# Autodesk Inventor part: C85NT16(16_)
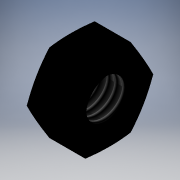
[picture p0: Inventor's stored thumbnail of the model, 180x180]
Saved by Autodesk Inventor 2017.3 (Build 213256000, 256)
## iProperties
Part Number: C85NT16(16_)
Material: Generic
Catalog Web Link: www.cadenas.de
Description: C85/CD85 ROD_NUT-ISO Standard Air Cylinder:Standard Type Double Acting Single Rod
Vendor: SMC
Document SubType Name: Modeling
Designer: partserver
Manufacturer: SMC
Mass: 0.332201 g
Surface Area: 3.72276 cm^2
Volume: 0.332201 cm^3
Density: 1 g/cm^3
Appearance: PSOLRGB-0-0-0
Category: PARTsolutions
Company: SMC
Title: C85NT16
Author: Cadenas PARTsolutions
Comments: ISO Standard Air Cylinder:Standard Type Double Acting Single Rod
PSOL_IDENT_0: {$CADENAS_DATA\23d-libs\smc_jp\actuator\standard_air_cylinder\c85\c85\parts\c85_rod_nut.prj},173 {VT
PSOL_IDENT_1: YP=3D},{NB=C85NT16(16_)},{LINA=C85NT16},{NN=C85/CD85 ROD_NUT},{DATE=09.12.2020 03:32:11},{GEOMDATE=2
PSOL_IDENT_2: 6.04.2020 05:22:00},{VERSION=},{LINEID=40},{WBVAR=OMSC},{WBNUMERIC=}  {NB=C85NT16(16_)},{LINA=C85NT1
PSOL_IDENT_3: 6},{KT=DUMMY},{MODEL=C85NT16},{BORE=16},{OMSC=},{KK=M6x1},{KKD=6.000},{KKJ=1.000},{SW=10},{H=5.0}
NB: C85NT16(16_)
NN: C85/CD85 ROD_NUT
NT: ISO Standard Air Cylinder:Standard Type Double Acting Single Rod
NBSYN: $MODEL.($BORE._$OMSC.)
LINA: C85NT16
CATALOG: SMC (JP
BORE: 16
OMSC: (-) Without order
KK: M6x1
KKD: 6
KKJ: 1
SW: 10
H: 5
SUPPLIER: SMC
ARTICLENO: C85NT16(16_)
BOMINFO: C85NT16
CREATOR: CADENAS GmbH
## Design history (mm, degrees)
sketch "Sketch_1"
  geometry: L1 (5, 0)-(0, 0); L2 (0, 5)-(0, 3); L3 (0, 3)-(0.542, 2.458); L4 (0.542, 2.458)-(4.458, 2.458); L5 (4.458, 2.458)-(5, 3); L6 (5, 3)-(5, 5); L7 (5, 5)-(2.5, 14.33); L8 (2.5, 14.33)-(0, 5)
  constraints: 16 end point
revolve "Revolution1" sketch "Sketch_1" stored, may be unused: angle "d0" = 360 deg
thread "Thread1" dims "d1" = 3.917, "d2" = 0
sketch "Sketch_2"
  geometry: L1 (-2.887, 5)-(-5.774, 0); L2 (-5.774, 0)-(-2.887, -5); L3 (-2.887, -5)-(2.887, -5); L4 (2.887, -5)-(5.774, 0); L5 (5.774, 0)-(2.887, 5); L6 (2.887, 5)-(-2.887, 5); C1 r 15 at (0, 0); 1 further point
  constraints: 12 end point, 1 centre point
extrude "Extrusion1" cut sketch "Sketch_2" distance "d3" = 5; taper "d4" = 0 deg
node "RODNUT_ROD_XY"
node "RODNUT_ROD_YZ"
node "RODNUT_ROD_ZX"
node "RODNUT_ROD_X"
node "RODNUT_ROD_Y"
node "RODNUT_ROD_Z"
node "RODNUT_ROD_Center"
body "Solid1"
